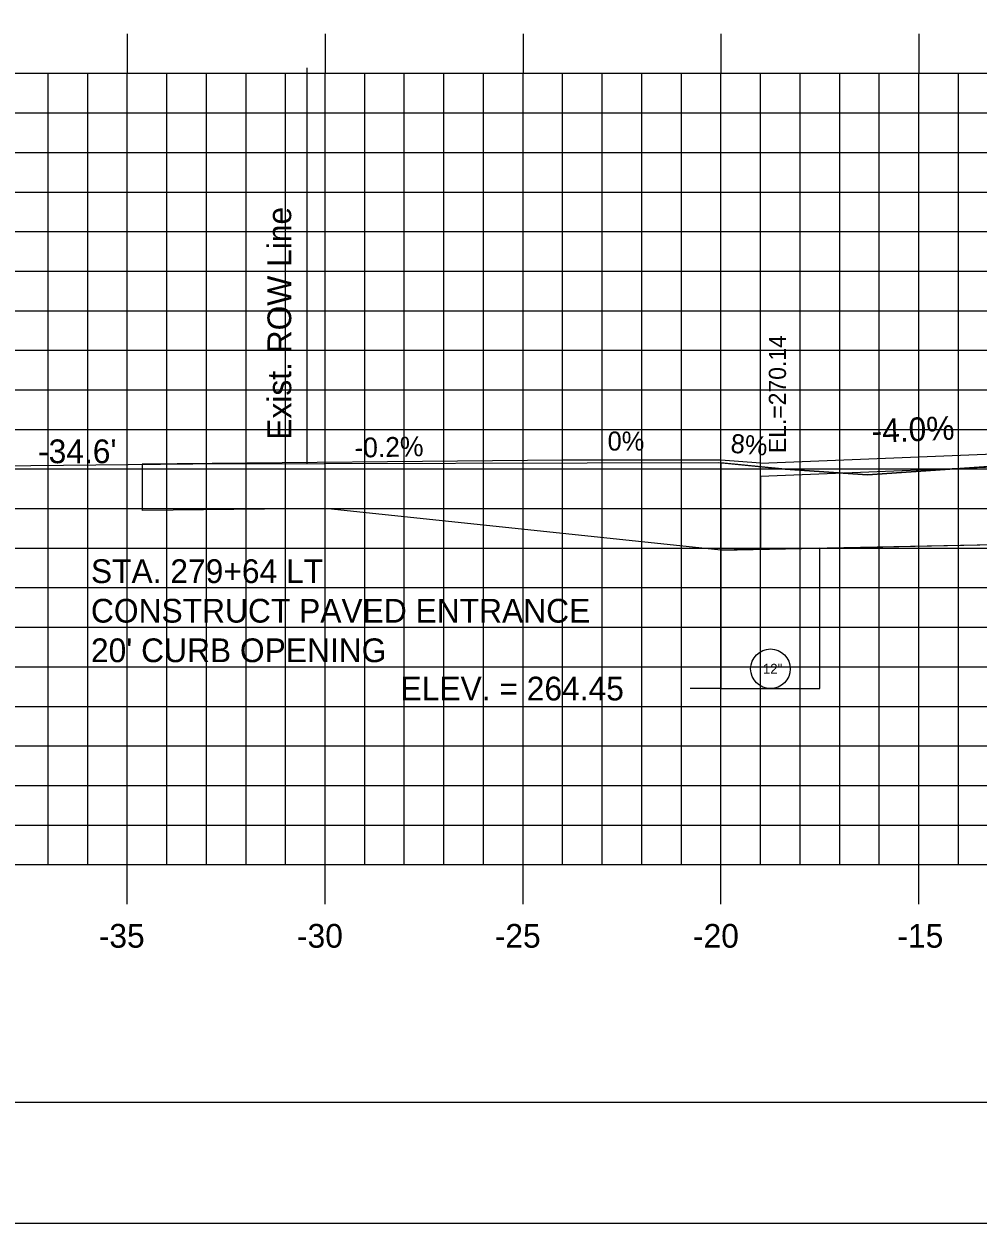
# Model space of a CAD drawing. Extents: x 855121 to 855291, y 366268 to 366378.
# Drawn here: x 855166.83 to 855190.94, y 366268.18 to 366298.48 of the extents above; entities that cross this region are included whole.
import ezdxf

# ---------------------------------------------------------------- set-up
doc = ezdxf.new("R2010")
doc.units = 0
for name, color, linetype in [('ANNOTATION', 7, 'Continuous'), ('BORDER', 7, 'Continuous'), ('D_Roadway_Drive_Gravel_LT', 7, 'Continuous'), ('D_Roadway_Drive_SubGrade', 7, 'Continuous'), ('D_Roadway_Edge_Shoulder', 7, 'Continuous'), ('D_Roadway_SubGrade', 7, 'Continuous'), ('D_Text_Monospaced', 7, 'Continuous'), ('D_Text_Standard', 7, 'Continuous'), ('E_ROW_Line', 7, 'Continuous'), ('H_V ANNOTATION', 7, 'Continuous'), ('JUNK COM EXC', 7, 'Continuous'), ('junk strct exc', 7, 'Continuous'), ('MAJOR', 7, 'Continuous'), ('MINOR', 7, 'Continuous'), ('PDRAIN', 7, 'Continuous'), ('PLOT BOUNDARY', 7, 'Continuous'), ('S_Roadway_Centerline', 7, 'Continuous')]:
    doc.layers.add(name, color=color, linetype=linetype)

msp = doc.modelspace()

# ---------------------------------------------------------------- linework, layer by layer
at = {"layer": 'BORDER'}
msp.add_line((855129.442, 366271.236), (855289.442, 366271.236), dxfattribs=at)
at = {"layer": 'D_Roadway_Drive_Gravel_LT'}
for p, q in [((855184.442, 366287.46), (855180.442, 366287.46)), ((855185.442, 366287.38), (855184.442, 366287.46))]:
    msp.add_line(p, q, dxfattribs=at)
at = {"layer": 'D_Roadway_Drive_SubGrade'}
for p, q in [((855180.442, 366287.46), (855169.821, 366287.355)), ((855169.821, 366287.355), (855169.821, 366286.189)), ((855185.442, 366287.048), (855185.442, 366287.381)), ((855174.442, 366286.234), (855169.833, 366286.189)), ((855184.442, 366285.187), (855174.442, 366286.234)), ((855185.442, 366285.207), (855184.442, 366285.187))]:
    msp.add_line(p, q, dxfattribs=at)
at = {"layer": 'D_Roadway_Edge_Shoulder'}
msp.add_lwpolyline([(855185.442, 366287.381), (855193.442, 366287.701), (855204.442, 366287.921), (855215.442, 366287.701), (855223.442, 366287.381)], dxfattribs=at)
at = {"layer": 'D_Roadway_SubGrade'}
msp.add_lwpolyline([(855193.442, 366287.368), (855185.442, 366287.048), (855185.442, 366285.208), (855193.442, 366285.368)], close=True, dxfattribs=at)
at = {"layer": 'D_Text_Standard'}
msp.add_lwpolyline([(855184.442, 366281.686), (855184.346, 366281.686), (855183.666, 366281.686)], dxfattribs=at)
at = {"layer": 'E_ROW_Line'}
msp.add_line((855173.984, 366287.375), (855173.984, 366297.375), dxfattribs=at)
at = {"layer": 'JUNK COM EXC'}
msp.add_lwpolyline([(855184.442, 366287.392), (855184.442, 366285.187), (855193.442, 366285.368), (855204.442, 366285.588), (855215.442, 366285.368), (855224.442, 366285.187), (855224.443, 366286.975), (855228.448, 366287.055), (855228.448, 366287.936), (855226.977, 366287.924), (855224.442, 366287.797), (855223.319, 366287.74), (855221.589, 366287.744), (855215.888, 366287.856), (855210.431, 366287.929), (855205.043, 366287.951), (855195.623, 366287.546), (855194.227, 366287.484), (855191.456, 366287.318), (855188.148, 366287.092), (855186.064, 366287.235)], close=True, dxfattribs=at)
at = {"layer": 'junk strct exc'}
msp.add_lwpolyline([(855184.442, 366285.187), (855184.442, 366281.686), (855186.942, 366281.686), (855186.942, 366285.238)], close=True, dxfattribs=at)
at = {"layer": 'MAJOR'}
for p, q in [((855169.442, 366298.238), (855169.442, 366297.236)), ((855174.442, 366298.238), (855174.442, 366297.236)), ((855179.442, 366298.238), (855179.442, 366297.236)), ((855184.442, 366298.238), (855184.442, 366297.236)), ((855189.442, 366298.238), (855189.442, 366297.236)), ((855134.442, 366297.236), (855274.442, 366297.236)), ((855134.442, 366297.236), (855274.442, 366297.236)), ((855169.442, 366277.236), (855169.442, 366297.236)), ((855174.442, 366277.236), (855174.442, 366297.236)), ((855179.442, 366277.236), (855179.442, 366297.236)), ((855184.442, 366277.236), (855184.442, 366297.236)), ((855189.442, 366277.236), (855189.442, 366297.236)), ((855134.442, 366292.236), (855274.442, 366292.236)), ((855134.442, 366287.236), (855274.442, 366287.236)), ((855134.442, 366282.236), (855274.442, 366282.236)), ((855134.442, 366277.236), (855274.442, 366277.236)), ((855134.442, 366277.236), (855274.442, 366277.236)), ((855169.442, 366276.234), (855169.442, 366277.236)), ((855174.442, 366276.234), (855174.442, 366277.236)), ((855179.442, 366276.234), (855179.442, 366277.236)), ((855184.442, 366276.234), (855184.442, 366277.236)), ((855189.442, 366276.234), (855189.442, 366277.236))]:
    msp.add_line(p, q, dxfattribs=at)
at = {"layer": 'MINOR'}
for p, q in [((855167.442, 366277.236), (855167.442, 366297.236)), ((855168.442, 366277.236), (855168.442, 366297.236)), ((855170.442, 366277.236), (855170.442, 366297.236)), ((855171.442, 366277.236), (855171.442, 366297.236)), ((855172.442, 366277.236), (855172.442, 366297.236)), ((855173.442, 366277.236), (855173.442, 366297.236)), ((855175.442, 366277.236), (855175.442, 366297.236)), ((855176.442, 366277.236), (855176.442, 366297.236)), ((855177.442, 366277.236), (855177.442, 366297.236)), ((855178.442, 366277.236), (855178.442, 366297.236)), ((855180.442, 366277.236), (855180.442, 366297.236)), ((855181.442, 366277.236), (855181.442, 366297.236)), ((855182.442, 366277.236), (855182.442, 366297.236)), ((855183.442, 366277.236), (855183.442, 366297.236)), ((855185.442, 366277.236), (855185.442, 366297.236)), ((855186.442, 366277.236), (855186.442, 366297.236)), ((855187.442, 366277.236), (855187.442, 366297.236)), ((855188.442, 366277.236), (855188.442, 366297.236)), ((855190.442, 366277.236), (855190.442, 366297.236)), ((855134.442, 366296.236), (855274.442, 366296.236)), ((855134.442, 366295.236), (855274.442, 366295.236)), ((855134.442, 366294.236), (855274.442, 366294.236)), ((855134.442, 366293.236), (855274.442, 366293.236)), ((855134.442, 366291.236), (855274.442, 366291.236)), ((855134.442, 366290.236), (855274.442, 366290.236)), ((855134.442, 366289.236), (855274.442, 366289.236)), ((855134.442, 366288.236), (855274.442, 366288.236)), ((855134.442, 366286.236), (855274.442, 366286.236)), ((855134.442, 366285.236), (855274.442, 366285.236)), ((855134.442, 366284.236), (855274.442, 366284.236)), ((855134.442, 366283.236), (855274.442, 366283.236)), ((855134.442, 366281.236), (855274.442, 366281.236)), ((855134.442, 366280.236), (855274.442, 366280.236)), ((855134.442, 366279.236), (855274.442, 366279.236)), ((855134.442, 366278.236), (855274.442, 366278.236))]:
    msp.add_line(p, q, dxfattribs=at)
at = {"layer": 'PDRAIN'}
msp.add_lwpolyline([(855184.442, 366285.187), (855184.442, 366281.686), (855186.942, 366281.686), (855186.942, 366285.187)], dxfattribs=at)
msp.add_circle((855185.692, 366282.186), 0.5, dxfattribs=at)
at = {"layer": 'PLOT BOUNDARY'}
msp.add_lwpolyline([(855121.349, 366268.177), (855291.349, 366268.177), (855291.349, 366378.177), (855121.349, 366378.177)], close=True, dxfattribs=at)
at = {"layer": 'S_Roadway_Centerline'}
msp.add_lwpolyline([(855157.182, 366287.226), (855171.097, 366287.369), (855184.381, 366287.398), (855186.064, 366287.235), (855188.148, 366287.092), (855191.456, 366287.318), (855194.227, 366287.484), (855195.623, 366287.546), (855205.043, 366287.951), (855210.431, 366287.929), (855215.888, 366287.856), (855221.589, 366287.744), (855223.319, 366287.74), (855226.977, 366287.924), (855228.12, 366287.931), (855237.955, 366288.101)], dxfattribs=at)

# ---------------------------------------------------------------- texts
at = {"layer": 'ANNOTATION'}
msp.add_text('-4.0%', height=0.6, rotation=2.2906, dxfattribs=at).set_placement((855188.258, 366287.894))
for s, p in [('STA. 279+64 LT', (855168.524, 366284.353)), ('CONSTRUCT PAVED ENTRANCE', (855168.524, 366283.353)), ("20' CURB OPENING", (855168.524, 366282.353))]:
    msp.add_text(s, height=0.6, dxfattribs=at).set_placement(p)
at = {"layer": 'D_Roadway_Drive_Gravel_LT'}
msp.add_text('0%', height=0.48, dxfattribs=at).set_placement((855181.578, 366287.701))
msp.add_text('8%', height=0.48, rotation=355.4261, dxfattribs=at).set_placement((855184.673, 366287.648))
at = {"layer": 'D_Text_Monospaced'}
msp.add_text('-0.2%', height=0.5, rotation=1.2678, dxfattribs=at).set_placement((855175.185, 366287.522))
at = {"layer": 'D_Text_Standard'}
msp.add_text(' EL.=270.14', height=0.4335, rotation=90, dxfattribs=at).set_placement((855186.085, 366287.475))
for s, p in [("-34.6'", (855167.188, 366287.382)), ('ELEV. = 264.45', (855176.346, 366281.386))]:
    msp.add_text(s, height=0.6, dxfattribs=at).set_placement(p)
at = {"layer": 'E_ROW_Line'}
msp.add_text('Exist. ROW Line', height=0.6, rotation=90, dxfattribs=at).set_placement((855173.584, 366287.975))
at = {"layer": 'H_V ANNOTATION'}
for s, p in [('-35', (855168.722, 366275.136)), ('-30', (855173.73, 366275.136)), ('-25', (855178.727, 366275.136)), ('-20', (855183.735, 366275.136)), ('-15', (855188.899, 366275.136))]:
    msp.add_text(s, height=0.6, dxfattribs=at).set_placement(p)
at = {"layer": 'PDRAIN'}
msp.add_text('12"', height=0.25, dxfattribs=at).set_placement((855185.501, 366282.061))

doc.saveas('drawing.dxf')
